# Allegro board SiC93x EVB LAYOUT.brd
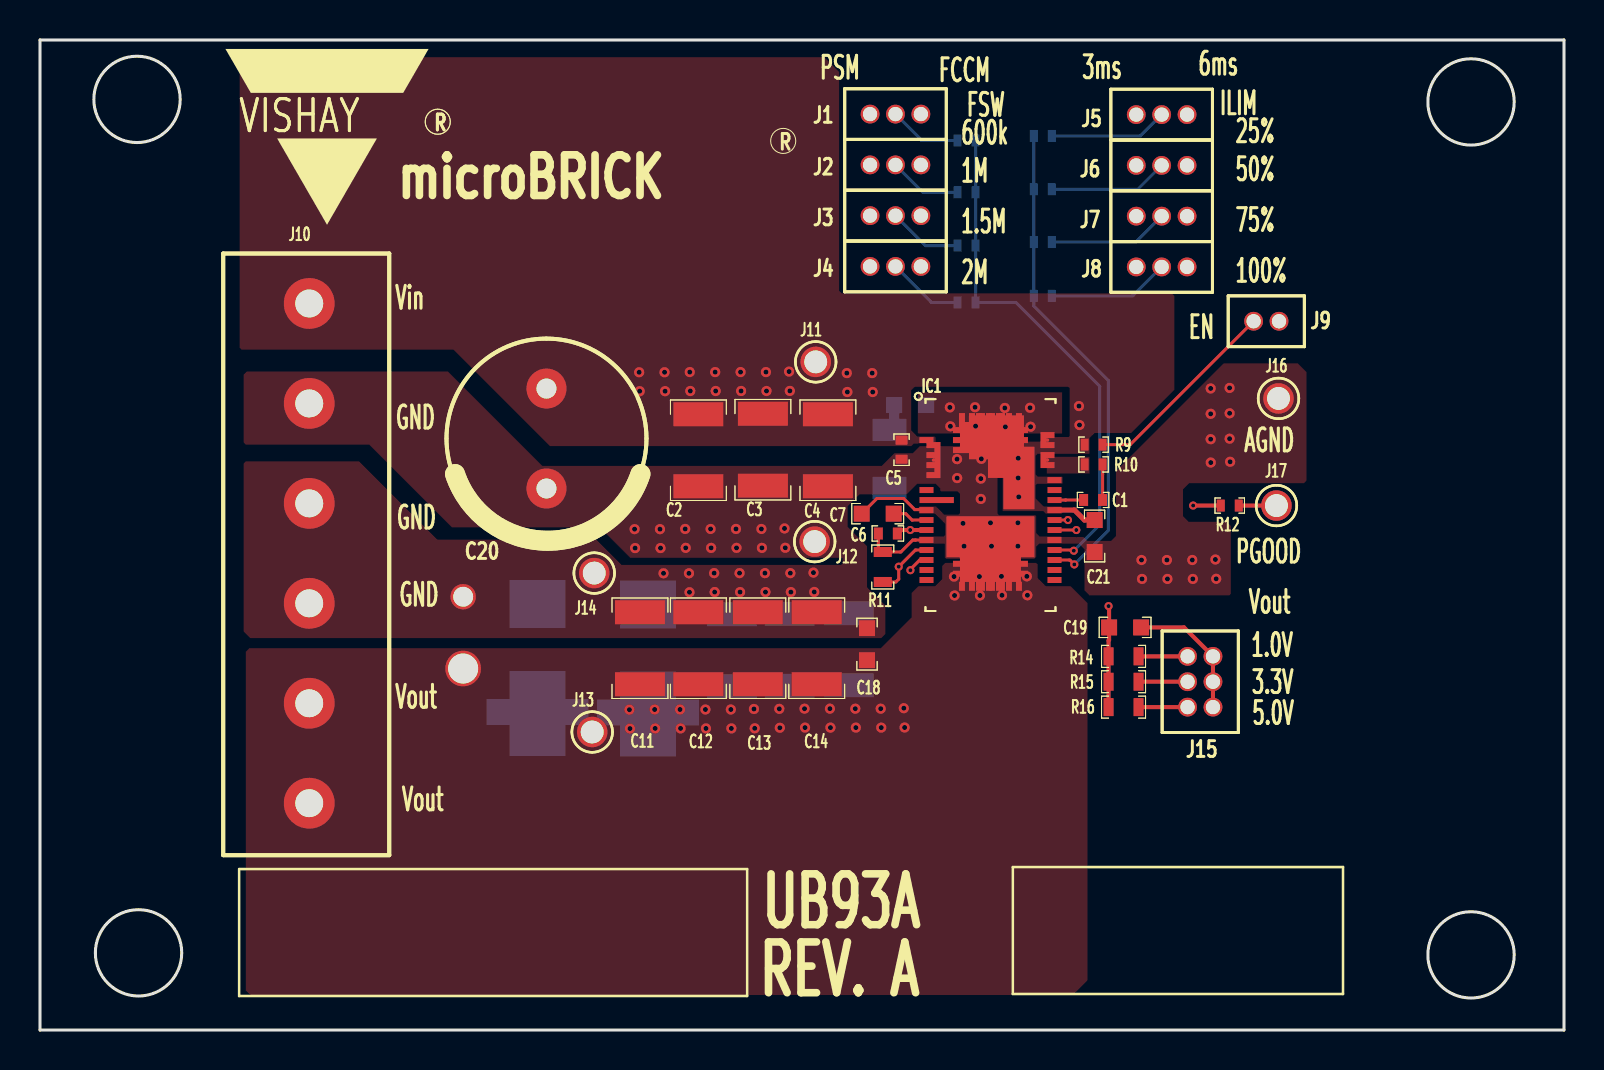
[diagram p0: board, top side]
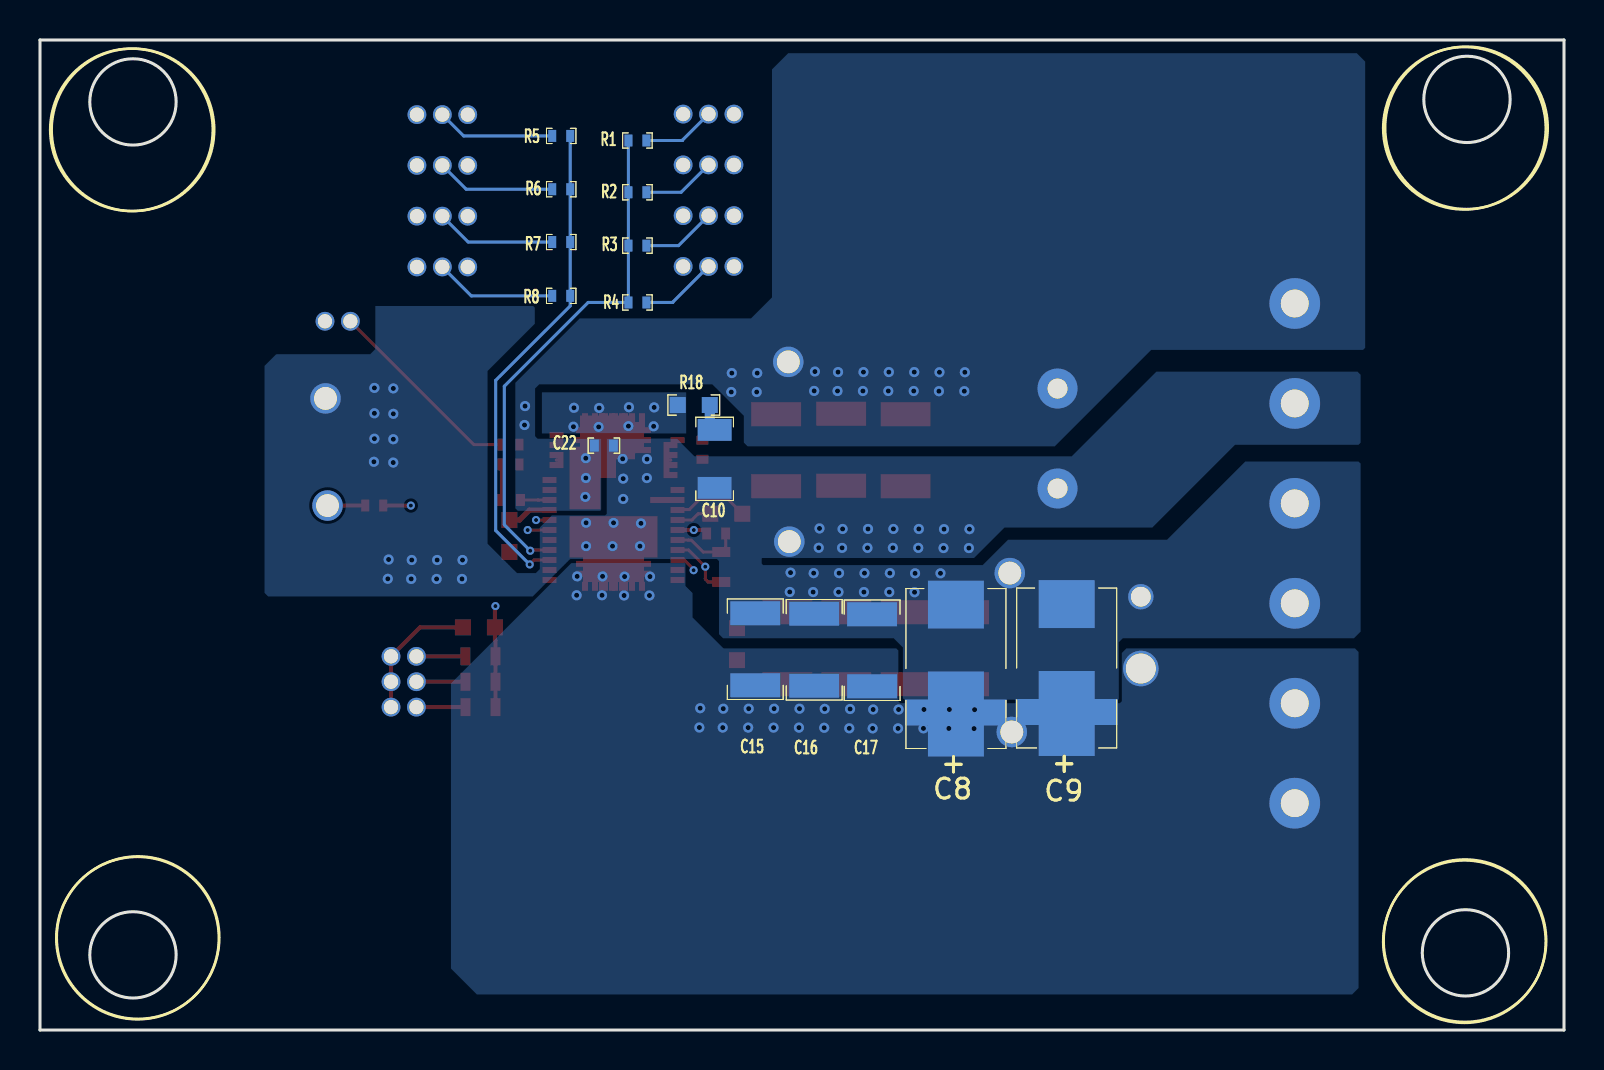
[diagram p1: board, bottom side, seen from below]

Outline 76.2 x 49.53 mm; copper layers: TOP, LAYER2, LAYER3, LAYER4, LAYER5, BOTTOM. Coordinates in mm from the lower left corner of the outline.
Outline path: circle c4.85,46.56 r2.16 ; circle c4.93,3.86 r2.16 ; circle c71.55,46.43 r2.16 ; circle c71.55,3.76 r2.16 ; 0,49.53 76.2,49.53 76.2,0 0,0 0,49.53

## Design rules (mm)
constraint set DEFAULT: min track width 0.152

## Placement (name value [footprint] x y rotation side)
C1  100n  [C0402-TDK1]  52.65 26.52 180 top
C2  22uF  [C1210-TDK]  32.92 29.01 270 top
C3  22uF  [C1210-TDK]  36.14 29.03 270 top
C4  22uF  [C1210-TDK]  39.4 29.01 270 top
C5  0.1uF  [C0402-TDK]  43.08 29.03 270 top
C6  0.1u  [C0402-TDK1]  42.39 24.84 180 top
C7  1u  [C0603-TDK1]  41.88 25.83 180 top
C8  DNP  [POSCAP]  30.4 18.08 90 bottom
C9  DNP  [POSCAP]  24.87 18.11 90 bottom
C10  DNP  [C0603-TDK1]  43.51 31.27 180 bottom
C11  22uF  [C1210-TDK]  30 19.1 90 top
C12  22uF  [C1210-TDK]  32.92 19.1 90 top
C13  22uF  [C1210-TDK]  35.89 19.1 90 top
C14  22uF  [C1210-TDK]  38.84 19.1 90 top
C15  22uF  [C1210-TDK]  40.44 19.05 90 bottom
C16  22uF  [C1210-TDK]  37.49 19.02 90 bottom
C17  22uF  [C1210-TDK]  34.59 19 90 bottom
C18  0.1u  [C0603-TDK1]  41.35 19.3 90 top
C19  22n  [C0603-TDK1]  54.25 20.14 180 top
C20  220uF  [CAP10P2X5]  25.32 29.59 270 top
C21  1u  [C0603-TDK1]  52.73 24.71 90 top
C22  0.1uF  [C0402-TDK]  48.01 29.24 180 bottom
IC1  SiC931  [SIC931A]  47.52 26.26 0 top
J1  CON3  [MINIJUMPER3]  44.04 45.82 180 top
J2  CON3  [MINIJUMPER3]  44.04 43.28 180 top
J3  CON3  [MINIJUMPER3]  44.04 40.74 180 top
J4  CON3  [MINIJUMPER3]  44.04 38.2 180 top
J5  CON3  [MINIJUMPER3]  57.35 45.8 180 top
J6  CON3  [MINIJUMPER3]  57.35 43.26 180 top
J7  CON3  [MINIJUMPER3]  57.35 40.72 180 top
J8  CON3  [MINIJUMPER3]  57.35 38.18 180 top
J9  CON2  [MINIJUMPER2]  60.68 35.46 0 top
J10  -  [CON6]  13.46 36.35 270 top
J11  VIN+s  [TP30]  38.79 33.43 0 top
J12  VIN-S  [TP30]  38.73 24.43 0 top
J13  VO+S  [TP30]  27.61 14.91 0 top
J14  VO-S  [TP30]  27.71 22.86 0 top
J15  CON6A  [MINIJUMPER2X3]  57.38 18.69 0 top
J16  AGND  [TP30]  61.93 31.6 0 top
J17  PGOOD  [TP30]  61.82 26.24 0 top
NOREF  -  []  -4.04 43.05 0 top
PB  CON2  [2PROBE]  21.16 18.08 135 top
R1  51k  [R0402-VISHAY1]  46.33 44.5 180 bottom
R2  100k  [R0402-VISHAY1]  46.33 41.91 180 bottom
R3  200k  [R0402-VISHAY1]  46.33 39.24 180 bottom
R4  510k  [R0402-VISHAY1]  46.33 36.4 180 bottom
R5  51k  [R0402-VISHAY1]  50.14 44.73 0 bottom
R6  100k  [R0402-VISHAY1]  50.14 42.06 0 bottom
R7  200k  [R0402-VISHAY1]  50.14 39.42 0 bottom
R8  510k  [R0402-VISHAY1]  50.14 36.73 0 bottom
R9  100k  [R0402-VISHAY1]  52.68 29.29 180 top
R10  0  [R0402-VISHAY1]  52.68 28.3 180 top
R11  10k  [R0603-VISHAY]  42.14 23.16 90 top
R12  100k  [R0402-VISHAY1]  59.49 26.24 180 top
R14  6.65k  [R0603-VISHAY]  54.18 18.69 0 top
R15  45.3k  [R0603-VISHAY]  54.18 17.42 0 top
R16  73.2  [R0603-VISHAY]  54.18 16.15 0 top
R18  DNP  [R1206-VISHAY]  42.47 28.57 90 bottom

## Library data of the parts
C1-C6 C11-C19 C21 C22 = CAPACITOR NON-POL
C7 C10 = CAP NP
C8 C9 = POSCAP
C20 = CAP
IC1 = SiC931
J1-J8 = CON3: User Part Number: ***
J9 = CON2: User Part Number: ***
J10 = CON6
J11-J14 J16 J17 = CON1
J15 = CON6A
PB = CON2
R1-R8 R10 R12 R14-R16 = R
R9 R11 R18 = RESISTOR

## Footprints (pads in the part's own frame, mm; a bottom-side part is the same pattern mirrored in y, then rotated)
2PROBE
  round 1.778 hole 1.499: 1(0,0)
  round 1.27 hole 0.991: 2(2.54,-2.54)
C0402-TDK
  rect 0.45x0.6 smd: 1(-0.475,0) 2(0.475,0)
C0402-TDK1
  rect 0.45x0.6 smd: 1(-0.475,0) 2(0.475,0)
C0603-TDK1
  rect 0.8x0.8 smd: 1(-0.8,0) 2(0.8,0)
C1210-TDK
  rect 1.2x2.5 smd: 1(-1.8,0) 2(1.8,0)
CAP10P2X5
  round 2 hole 1: 1(-2.5,0) 2(2.5,0)
CON6
  round 2.54 hole 1.397: 1(0,0) 2(5,0) 3(10,0) 4(15,0) 5(20,0) 6(25,0)
MINIJUMPER2
  round 0.94 hole 0.711: 1(0,0) 2(1.27,0)
MINIJUMPER2X3
  round 0.94 hole 0.711: 1(0,0) 2(1.27,0) 3(0,-1.27) 4(1.27,-1.27) 5(0,-2.54) 6(1.27,-2.54)
MINIJUMPER3
  round 0.94 hole 0.711: 1(0,0) 2(1.27,0) 3(2.54,0)
POSCAP
  rect 2.4x2.8 smd: 1(-3.2,0) 2(3.2,0)
  custom 0.675x0.675 smd: 3(-1.5,0)
R0402-VISHAY1
  rect 0.4x0.6 smd: 1(-0.45,0) 2(0.45,0)
R0603-VISHAY
  rect 0.5x0.9 smd: 1(-0.75,0) 2(0.75,0)
R1206-VISHAY
  rect 1.1x1.7 smd: 1(-1.45,0) 2(1.45,0)
SIC931A
  custom 0.5x0.5 smd: 1(-0.15,3.6) 48(0.15,3.6)
  round 0 smd: 2(-3.124,4.242) 3(-3.124,3.759) 6(-3.048,2.261) 7(-3.048,1.778) 8(-3.048,1.295) 20(-3.099,-4.75) 21(-2.235,-5.156) 22(-1.727,-5.182) 23(-1.245,-5.182) 24(-0.737,-5.207) 25(-0.229,-5.207) 27(0.762,-5.334) 28(1.245,-5.309) 29(1.753,-5.309) 30(2.261,-5.309) 31(3.302,-4.775) 32(3.302,-4.267) 45(3.302,2.235) 47(3.277,3.251) 49(3.302,4.242) 50(3.277,4.724) 51(2.235,5.283) 52(1.778,5.283) 53(1.245,5.283) 54(0.762,5.258) 55(0.254,5.232) 56(-0.254,5.283) 57(-0.762,5.283) 58(-1.27,5.283) 59(-1.753,5.283) 60(-2.261,5.283)
  rect 0.7x0.3 smd: 4(-3.2,3.25) 9(-3.2,0.75) 11(-3.2,-0.25) 12(-3.2,-0.75) 13(-3.2,-1.25) 14(-3.2,-1.75) 15(-3.2,-2.25) 16(-3.2,-2.75) 17(-3.2,-3.25) 18(-3.2,-3.75) 33(3.2,-3.75) 34(3.2,-3.25) 35(3.2,-2.75) 36(3.2,-2.25) 37(3.2,-1.75) 38(3.2,-1.25) 39(3.2,-0.75) 40(3.2,-0.25) 41(3.2,0.25) 42(3.2,0.75) 43(3.2,1.25)
  custom 0.175x0.175 smd: 5(-2.85,2.25) 44(2.85,2.25) 46(2.85,3.25)
  rect 1.72x0.3 smd: 10(-2.69,0.25)
  custom 0.66x0.66 smd: 19(-0.15,-2.97) 26(0.15,-2.97)
  custom 0.688x0.688 smd: 61(0.3,2.92)
  rect 1.55x3.13 smd: 62(1.425,1.355)
  rect 4.4x2.06 smd: 63(0,-1.59)
TP30
  round 1.524 hole 1.143: 1(0,0)

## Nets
GND_POWER: C2.2 C3.2 C4.2 C5.2 C6.2 C7.2 C8.2 C8.3 C9.2 C9.3 C11.2 C12.2 C13.2 C14.2 C15.2 C16.2 C17.2 C18.2 C20.2 C21.1 C22.2 IC1.5 IC1.6 IC1.7 IC1.8 IC1.11 IC1.14 IC1.37 IC1.61 IC1.63 J1.3 J2.3 J3.3 J4.3 J5.3 J6.3 J7.3 J8.3 J9.2 J10.2 J10.3 J10.4 J12.1 J14.1 J16.1 PB.2 R11.2 R18.1
VDD1: C6.1 IC1.13 J1.1 J2.1 J3.1 J4.1 J5.1 J6.1 J7.1 J8.1 R12.2
VIN: C2.1 C3.1 C4.1 C5.1 C20.1 C21.2 C22.1 IC1.4 IC1.40 IC1.43 IC1.46 IC1.47 IC1.62 J10.1 J11.1 R9.2
BOOT: C1.2 IC1.41
MODE1: IC1.36 R1.1 R2.1 R3.1 R4.1
MODE2: IC1.35 R5.1 R6.1 R7.1 R8.1
PGD: IC1.39 J17.1 R12.1
PHASE: IC1.44 IC1.45 R10.2
VO: C8.1(P) C9.1(P) C11.1 C12.1 C13.1 C14.1 C15.1 C16.1 C17.1 C18.1 C19.2 IC1.16 IC1.19 IC1.20 IC1.21 IC1.22 IC1.23 IC1.24 IC1.25 IC1.26 IC1.27(VOUT9) IC1.28 IC1.29 IC1.30 IC1.31 IC1.32 J10.5 J10.6 J13.1 PB.1 R14.1 R15.1 R16.1
N10592056: J1.2 R1.2
N10592279: J2.2 R2.2
N10592308: J3.2 R3.2
N10592330: J4.2 R4.2
N10602058: J5.2 R5.2
N10602062: J6.2 R6.2
N10602066: J7.2 R7.2
N10602070: J8.2 R8.2
N10738499: C7.1 IC1.12
N10742884: J15.3 R15.2
N10742888: J15.5 R16.2
N10742896: J15.1 R14.2
N10742948: C19.1 IC1.15 J15.2 J15.4 J15.6 R11.1
N10743645: C1.1 R10.1
N10744089: C10.1 IC1.1 IC1.2 IC1.3 IC1.48 IC1.49 IC1.50 IC1.51 IC1.52 IC1.53 IC1.54 IC1.55 IC1.56 IC1.57 IC1.58 IC1.59 IC1.60
N10744769: C10.2 R18.2
N10747860: IC1.38 J9.1 R9.1

Pads without a net: IC1 9 10 17 18 33 34 42

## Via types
v1: diameter 0.406, hole 0.203, TOP to BOTTOM, 9 vias
v2: diameter 0.508, hole 0.254, TOP to BOTTOM, 117 vias

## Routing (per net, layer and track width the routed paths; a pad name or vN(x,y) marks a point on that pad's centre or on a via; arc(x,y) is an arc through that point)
GND_POWER: length 7.3
  TOP w0.152: C6.2 41.92,24.14 R11.2 43.04,23.91 43.64,24.51 43.77,24.51 43.77,24.51 IC1.14 ; C7.2 41.85,26.59 43.18,26.59 43.74,26.03 44.16,26.03 44.16,26.01 IC1.11
  vias: v2(29.73,25.06) v2(29.76,24.11) v2(31,25.06) v2(31.03,24.11) v2(31.18,22.85) v2(32.26,25.07) v2(32.29,24.12) v2(32.45,22.85) v2(32.47,21.9) v2(33.53,25.07) v2(33.56,24.12) v2(33.71,22.86) v2(33.73,21.91) v2(34.8,25.07) v2(34.83,24.12) v2(34.98,22.86) v2(35,21.91) v2(36.07,25.07) v2(36.1,24.12) v2(36.25,22.86) v2(36.27,21.91) v2(37.23,25.09) v2(37.26,24.13) v2(37.52,22.86) v2(37.54,21.91) v2(38.67,22.88) v2(38.71,21.92) v2(45.85,28.56) v2(45.86,27.61) v2(46.15,25.35) v2(46.2,24.21) v2(47.04,27.58) v2(47.04,26.57) v2(47.07,28.57) v2(47.52,25.37) v2(47.57,24.21) v2(48.9,25.37) v2(48.9,24.21) v2(55.07,23.51) v2(55.1,22.57) v2(56.34,23.51) v2(56.37,22.57) v2(57.61,23.51) v2(57.64,22.57) v2(58.53,32.1) v2(58.53,30.83) v2(58.53,29.56) v2(58.54,28.39) v2(58.77,23.54) v2(58.81,22.57) v2(59.48,32.12) v2(59.48,30.85) v2(59.48,29.58) v2(59.51,28.43)
VDD1: length 59.1
  TOP w0.203: IC1.13 v1(43.51,25.01) 43.04,25.01 C6.1 ; R12.2 v1(57.66,26.24)
  LAYER3 w0.152: J5.1 J6.1 J7.1 J8.1 57.35,35.86 ; v1(43.51,25.01) 44.45,25.95 57.37,25.95 v1(57.66,26.24) 57.66,35.56 57.35,35.86 ; 57.35,35.86 56.77,36.45 45.8,36.45 J4.1 J3.1 J2.1 J1.1
VIN: length 2.2
  TOP w0.254: IC1.40 51.72,26.01 52.22,25.51 C21.2
  vias: v2(29.96,32.91) v2(29.98,31.96) v2(31.23,32.91) v2(31.25,31.96) v2(32.49,32.92) v2(32.51,31.97) v2(33.76,32.92) v2(33.78,31.97) v2(35.03,32.92) v2(35.05,31.97) v2(36.3,32.92) v2(36.32,31.97) v2(37.45,32.94) v2(37.49,31.97) v2(40.34,32.87) v2(40.37,31.92) v2(41.61,32.87) v2(41.64,31.92) v2(48.91,28.61) v2(48.91,27.62) v2(48.94,26.67) v2(51.95,31.21) v2(51.97,30.27)
BOOT: length 1.5
  TOP w0.152: IC1.41 51.28,26.51 51.28,26.52 C1.2
MODE1: length 25.8
  TOP w0.152: IC1.36 51.65,24.01 v1(51.69,23.98)
  BOTTOM w0.152: v1(51.69,23.98) 52.98,25.27 52.98,32.21 48.79,36.4 R4.1 R3.1 R2.1 R1.1
MODE2: length 24.8
  TOP w0.152: v1(51.71,23.29) 51.49,23.51 IC1.35
  BOTTOM w0.152: R5.1 R6.1 R7.1 R8.1 49.69,36.23 53.42,32.5 53.42,24.99 v1(51.71,23.29)
PGD: length 15
  TOP w0.152: IC1.39 v1(51.4,25.51)
  TOP w0.203: J17.1 R12.1
  LAYER3 w0.152: v1(51.4,25.51) 51.11,25.23 51.11,24.73 51.38,24.46 60.05,24.46 J17.1
VO: length 39.8
  TOP w0.152: v1(43.52,23) 43.52,23.05 43.99,23.51 IC1.16
  TOP w0.203: R16.1 R15.1 R14.1 53.43,19.49 53.45,19.51 C19.2 53.45,21.18 v1(53.43,21.21)
  LAYER3 w0.152: J13.1 27.61,18.36 28.47,19.23 42.34,19.23 43.15,20.04 43.15,22.64 v1(43.52,23) 43.81,23.29 50.32,23.29 52.4,21.21 v1(53.43,21.21)
  vias: v2(29.47,16.03) v2(29.5,15.08) v2(30.73,16.04) v2(30.76,15.09) v2(32,16.04) v2(32.03,15.09) v2(33.27,16.04) v2(33.3,15.09) v2(34.54,16.04) v2(34.57,15.09) v2(35.7,16.06) v2(35.74,15.09) v2(36.97,16.07) v2(36.99,15.12) v2(38.23,16.08) v2(38.25,15.13) v2(39.5,16.08) v2(39.52,15.13) v2(40.77,16.08) v2(40.79,15.13) v2(42.04,16.08) v2(42.06,15.13) v2(43.19,16.1) v2(43.23,15.13) v2(45.7,22.69) v2(45.73,21.74) v2(46.97,22.69) v2(47,21.74) v2(48.07,22.7) v2(48.1,21.75) v2(49.34,22.7) v2(49.37,21.75)
N10592056: length 3.7
  BOTTOM w0.152: R1.2 44.07,44.5 44.07,44.52 J1.2
N10592279: length 3.7
  BOTTOM w0.152: R2.2 44.15,41.91 J2.2
N10592308: length 3.7
  BOTTOM w0.152: J3.2 44.27,39.24 R3.2
N10592330: length 3.9
  BOTTOM w0.152: R4.2 44.56,36.4 44.56,36.41 J4.2
N10602058: length 5.9
  BOTTOM w0.152: J5.2 55.02,44.73 R5.2
N10602062: length 6
  BOTTOM w0.152: J6.2 54.89,42.06 R6.2
N10602066: length 6
  BOTTOM w0.152: R7.2 54.79,39.42 J7.2
N10602070: length 6.1
  BOTTOM w0.152: J8.2 54.64,36.73 R8.2
N10738499: length 1.8
  TOP w0.152: IC1.12 43.61,25.51 43.29,25.83 C7.1
N10742884: length 2.5
  TOP w0.203: J15.3 R15.2
N10742888: length 2.5
  TOP w0.203: J15.5 R16.2
N10742896: length 2.5
  TOP w0.203: J15.1 R14.2
N10742948: length 27.9
  TOP w0.152: IC1.15 43.77,24.01 v1(42.94,23.18) 42.94,22.56 42.79,22.41 R11.1
  TOP w0.203: C19.1 57.2,20.14 J15.2 J15.4 J15.6
  LAYER3 w0.152: J15.2 55.52,21.82 52.48,21.82 50.62,23.67 43.43,23.67 v1(42.94,23.18)
N10743645: length 1.8
  TOP w0.152: R10.1 53.13,27.79 C1.1
N10744089:
  vias: v2(45.49,31.15) v2(45.52,30.2) v2(46.75,31.16) v2(46.78,30.21) v2(48.24,31.12) v2(48.27,30.17) v2(49.5,31.13) v2(49.53,30.18)
N10744769: length 1.3
  BOTTOM w0.508: C10.2 42.71,30.27 R18.2
N10747860: length 29.2
  TOP w0.152: J9.1 54.51,29.29 R9.1 ; v1(51.82,25.01) IC1.38
  LAYER3 w0.152: v1(51.82,25.01) 58.39,25.01 60.68,27.3 J9.1

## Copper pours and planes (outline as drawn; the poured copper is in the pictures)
GND_POWER on TOP: outline of 98 points within 10.19,19.61 63.32,33.35
GND_POWER on BOTTOM: 10.32,32.93 20.38,32.93 24.61,28.7 43.48,28.7 44.37,29.59 47.85,29.59 47.86,29.58 47.86,25.82 47.94,25.75 50.61,25.75 51.21,25.15 51.21,23.06 51.41,22.86 52.35,22.86 53.82,24.33 53.82,32.97 51.46,35.33 51.46,36.14 51.54,36.22 59.44,36.22 59.44,34.06 59.69,33.81 64.39,33.81 64.97,33.22 64.97,21.87 64.8,21.69 51.56,21.69 51.13,22.12 51.13,22.13 49.69,23.56 42.35,23.56 42.25,23.46 42.25,19.8 42.05,19.6 33.51,19.6 33.06,19.14 33.06,16.6 32.98,16.53 22.29,16.53 22.26,16.55 22.26,19.4 22.06,19.6 10.5,19.6 10.17,19.93 10.17,28.34 10.27,28.44 15.94,28.44 19.85,24.53 27.8,24.53 29.07,23.26 40.04,23.26 40.12,23.33 40.12,23.59 40.09,23.61 29.5,23.61 27.98,25.14 20.58,25.14 16.44,29.28 10.27,29.28 10.17,29.38 10.17,32.78
GND_POWER on LAYER2: 10.17,2.25 9.94,2.48 9.94,28.46 15.96,28.46 19.82,24.6 27.7,24.6 29.04,23.25 40.14,23.25 40.19,23.31 40.19,23.66 40.14,23.71 29.53,23.71 28.08,25.16 20.97,25.16 16.62,29.5 9.94,29.5 9.94,46.75 10.27,47.08 39.84,47.08 39.89,47.03 39.89,36.01 43.55,32.35 50.2,32.35 50.94,31.61 50.94,26.71 50.38,26.15 44.72,26.15 44.23,25.67 44.23,3.06 43.42,2.25
GND_POWER on LAYER2: 40.75,47.05 40.8,47.11 41.82,47.11 42,46.93 42,37.22 42.2,37.02 45.31,37.02 46.12,37.83 46.12,47.18 55.31,47.18 55.38,47.11 55.38,36.74 55.41,36.74 55.74,36.41 62.42,36.41 62.57,36.26 62.57,34.56 62.47,34.46 61.81,34.46 61.43,34.84 61.43,35.8 61.15,36.08 60.11,36.08 59.63,35.6 59.63,34.15 60.74,33.03 63.54,33.03 63.64,32.93 63.64,3.24 63.11,2.71 46.54,2.71 45.15,4.1 45.15,25.72 45.22,25.79 51.09,25.79 51.57,26.28 51.57,31.79 50.63,32.73 45.02,32.73 40.75,37
GND_POWER on LAYER3: 10.34,32.94 20.4,32.94 25.12,28.22 43,28.22 43.99,29.21 47.85,29.21 47.88,29.18 47.88,25.83 47.96,25.76 50.83,25.76 50.85,25.73 50.85,24.03 50.72,23.9 43.33,23.9 43,23.57 42.37,23.57 42.27,23.47 42.27,19.68 42.14,19.56 10.57,19.56 10.19,19.94 10.19,28.35 10.29,28.45 15.95,28.45 19.86,24.54 27.81,24.54 29.08,23.27 40.06,23.27 40.13,23.34 40.13,23.6 40.11,23.62 29.51,23.62 27.99,25.15 20.6,25.15 16.46,29.29 10.29,29.29 10.19,29.39 10.19,32.79
GND_POWER on LAYER4: 40.77,47.04 40.82,47.09 41.83,47.09 42.01,46.91 42.01,37.21 42.21,37.01 45.32,37.01 46.13,37.82 46.13,47.17 55.32,47.17 55.4,47.09 55.4,36.73 55.42,36.73 55.75,36.4 62.43,36.4 62.59,36.25 62.59,34.54 62.48,34.44 61.82,34.44 61.44,34.82 61.44,35.79 61.16,36.07 60.12,36.07 59.64,35.59 59.64,34.14 60.76,33.02 63.55,33.02 63.65,32.92 63.65,3.23 63.12,2.69 46.56,2.69 45.16,4.09 45.16,25.7 45.24,25.78 51.1,25.78 51.59,26.26 51.59,31.78 50.65,32.72 45.03,32.72 40.77,36.98
GND_POWER on LAYER4: 10.19,2.24 9.96,2.46 9.96,28.45 15.98,28.45 19.84,24.59 27.71,24.59 29.06,23.24 40.16,23.24 40.21,23.29 40.21,23.65 40.16,23.7 29.54,23.7 28.09,25.15 20.98,25.15 16.64,29.49 9.96,29.49 9.96,46.74 10.29,47.07 39.85,47.07 39.9,47.02 39.9,35.99 43.56,32.33 50.22,32.33 50.95,31.6 50.95,26.7 50.39,26.14 44.73,26.14 44.25,25.65 44.25,3.05 43.43,2.24
GND_POWER on LAYER5: 10.34,32.93 20.4,32.93 25.12,28.21 43,28.21 43.99,29.2 47.85,29.2 47.88,29.17 47.88,25.82 47.96,25.74 49.76,25.74 49.81,25.69 49.81,23.66 49.71,23.56 42.37,23.56 42.27,23.46 42.27,19.61 42.14,19.48 10.63,19.48 10.19,19.93 10.19,28.33 10.29,28.43 15.95,28.43 19.86,24.52 27.81,24.52 29.08,23.25 40.06,23.25 40.13,23.33 40.13,23.58 40.11,23.61 29.52,23.61 27.99,25.13 20.6,25.13 16.46,29.27 10.29,29.27 10.19,29.37 10.19,32.78
VIN on TOP: 50.09,29.44 50.32,29.67 51.44,29.67 51.49,29.72 51.49,32.11 51.41,32.18 43.74,32.18 43.56,32 43.56,30 43.87,29.69 44.73,29.69 44.78,29.64 44.78,29.39 44.73,29.34 43.69,29.34 43.56,29.21 25.5,29.21 20.68,34.04 10.08,34.04 9.98,34.14 9.98,48.36 10.29,48.67 39.22,48.67 39.95,47.93 39.95,36.98 40.08,36.86 56.59,36.86 56.72,36.73 56.72,32.03 54.56,29.87 52.73,29.87 52.48,29.62 52.48,28.85 52.45,28.83 49.89,28.83 49.78,28.73 49.78,27.79 49.89,27.69 51.1,27.69 51.13,27.66 51.13,27.36 51.1,27.33 49.86,27.33 49.78,27.25 49.78,26.59 50.19,26.19 51.08,26.19 51.1,26.16 51.1,25.86 51.08,25.83 50.29,25.83 50.16,25.96 48.16,25.96 48.13,25.98 48.13,29.39 48.18,29.44
VIN on BOTTOM: 48.14,26.03 48.14,29.56 48.17,29.58 51.32,29.58 51.45,29.71 51.45,32.1 51.24,32.3 42.58,32.3 41.01,30.73 41.01,29.39 40.82,29.2 25.46,29.2 20.64,34.03 10.04,34.03 9.94,34.13 9.94,48.45 10.36,48.87 38.79,48.87 39.6,48.06 39.6,36.65 40.65,35.6 49.21,35.6 52.44,32.38 52.44,26.1 52.31,25.98 48.19,25.98
VIN on LAYER3: 48.16,26.24 48.16,29.49 48.06,29.59 43.74,29.59 43.36,29.21 25.48,29.21 20.65,34.04 10.06,34.04 9.96,34.14 9.96,48.41 10.26,48.72 39.55,48.72 39.98,48.29 39.98,36.68 41.05,35.61 56.52,35.61 56.74,35.38 56.74,26.42 56.52,26.19 48.21,26.19
VIN on LAYER5: 48.16,26.02 48.16,29.48 48.06,29.58 43.74,29.58 43.36,29.2 25.48,29.2 20.65,34.02 10.06,34.02 9.96,34.12 9.96,40.8 9.96,40.81 9.96,48.55 10.24,48.82 39.32,48.82 39.85,48.29 39.85,36.75 40.28,36.32 57.63,36.32 57.94,36.02 57.94,27.76 56.15,25.97 48.21,25.97
PHASE on TOP: 50.34,28.7 50.34,27.84 52.48,27.84 52.48,28.7
VO on TOP: 49.81,23.37 45.26,23.37 45.11,23.22 45.11,22.56 44.75,22.2 43.92,22.2 43.59,21.87 43.59,20.65 42.04,19.1 10.46,19.1 10.29,18.92 10.29,1.98 10.52,1.75 51.64,1.75 52.37,2.49 52.37,21.36 51.54,22.2 50.29,22.2 49.89,22.61 49.89,23.29
VO on BOTTOM: 49.63,23.36 43.95,23.36 43.93,23.33 43.93,22.22 43.57,21.86 43.57,20.64 42.02,19.09 33.39,19.09 33.28,18.99 33.28,16.45 33.18,16.35 22.21,16.35 22.11,16.45 22.11,18.86 21.88,19.09 10.45,19.09 10.27,18.91 10.27,2.1 10.59,1.78 54.36,1.78 55.65,3.07 55.65,17.34
VO on LAYER3: 29.24,18.9 28.75,18.41 28.75,14.02 28.58,13.84 26.64,13.84 26.44,14.05 26.44,18.41 25.96,18.9 10.59,18.9 10.29,18.59 10.29,1.98 10.52,1.75 54.2,1.75 55.25,2.79 55.25,17.73 49.96,23.01 44.07,23.01 43.7,22.64 43.7,20.28 42.32,18.9
VO on LAYER5: 43.97,23.35 43.94,23.33 43.94,22.86 42.64,21.56 42.64,19.69 42.23,19.28 10.66,19.28 10.29,18.91 10.29,2.01 10.52,1.78 55.19,1.78 55.78,2.36 55.78,17.94 50.37,23.35
N10744089 on TOP, BOTTOM: 51.1,29.84 51.1,31.9 43.89,31.9 43.89,29.84

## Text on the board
Ref Des/Silkscreen Top: R | Vin | Vout | GND | PSM | FCCM | 600k | 1M | 1.5M | 2M | FSW | 3ms | EN | 6ms | ILIM | 25% | 50% | 75% | 100% | PGOOD | AGND | 1.0V | 3.3V | 5.0V | microBRICK | REV. A | UB93A
FAB: Layer4 | Layer3 | Layer2 | Layer5 | Bottom | Top | TOTAL THICKNESS - 0.62 -.008/+.005 | 2OZ | 1 THIS IS A 6 LAYER BOARD WITH COMPONENTS ON BOTH SIDES. | 3 SILKSCREEN BOTH SIDES WITH WHITE NON CONDUCTIVE EPOXY BASED INK | 4 IMMERSION GOLD FINISH | 2 SMT LAND PATTERNS THAT HAVE A FINISHED PAD WIDTH RANGING FROM | 6 Material Type: IT175A | 5 GREEN SOLDER MASK | .012 TO .015 MUST USE THE FOLLOWING TOLERANCE, +.002-.0005. | PB VENDOR TO ADJUST ARTWORK TO COMPENSATE FOR ETCH PROCESS. | NOTES: UNLESS OTHERWISE SPECIFIED:
User.5: FIGURE | FINISHED_SIZE | 8.0 | 10.0 | 28.0 | 39.0 | 39.37 | 45.0 | 55.0 | 59.0 | DRILL CHART: TOP to BOTTOM | ALL UNITS ARE IN MILS | TOLERANCE_DRILL | +0.0/-0.0 | +2.0/-2.0 | +3.937/-3.937 | PLATED | QTY | 8 | 101 | 34 | 1 | 2 | 6 | 159 | TOTAL HOLES:
